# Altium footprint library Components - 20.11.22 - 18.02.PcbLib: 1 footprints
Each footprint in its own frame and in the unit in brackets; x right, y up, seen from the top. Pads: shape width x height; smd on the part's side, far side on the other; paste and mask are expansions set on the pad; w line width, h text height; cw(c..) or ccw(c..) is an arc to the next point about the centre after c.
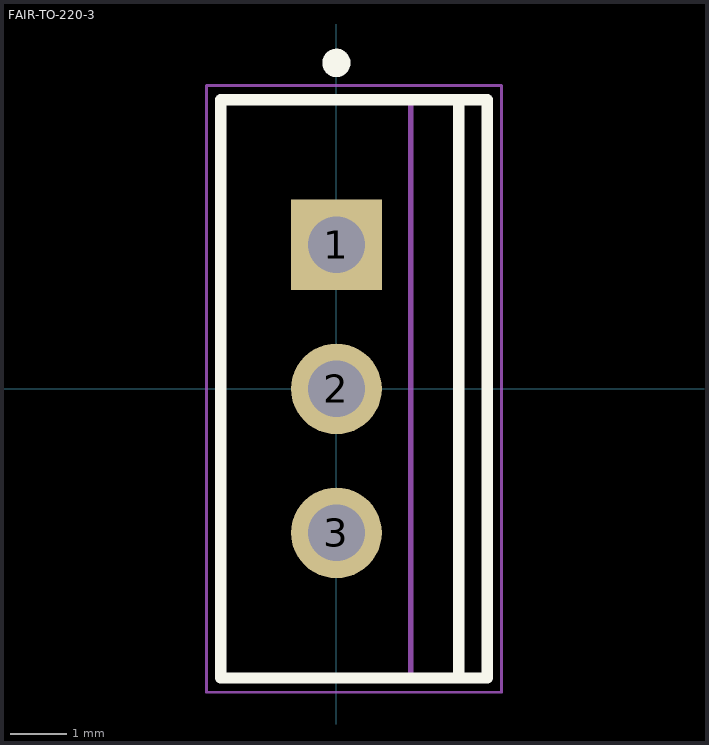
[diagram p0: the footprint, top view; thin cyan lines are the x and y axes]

## FAIR-TO-220-3 [mm] "FM, 3-Leads, Body 10.2x4.7mm, Pitch 2.54mm"
height 18.95
pads (3):
  rect 1.6x1.6 hole 1: 1(0,2.54)
  round 1.6 hole 1: 2(0,0) 3(0,-2.54)
Top Overlay:
  circle w0.25: c0,5.75 r0.125
  lines w0.2: 2.16,-5.1 2.16,5.1 ; -2.04,-5.1 -2.04,5.1 2.66,5.1 2.66,-5.1 -2.04,-5.1
Mechanical 13:
  lines w0.1: 1.31,-5.1 1.31,5.1 ; -2.04,-5.1 2.66,-5.1 2.66,5.1 -2.04,5.1 -2.04,-5.1
Mechanical 15:
  lines w0.05: -2.29,-5.35 2.91,-5.35 2.91,5.35 -2.29,5.35 -2.29,-5.35
  lines w0.1: -0.5,0 0.5,0 ; 0,-0.5 0,0.5
3D body: height 18.95, standoff 17.95, extent 1.31,-4.95 2.66,4.95
3D body: height 16.51, standoff 16.15, extent 1.31,-4.95 2.66,-1.8
3D body: height 16.51, standoff 16.15, extent 1.31,1.8 2.66,4.95
3D body: height 16.15, standoff 15.8, extent 1.31,-4.95 2.66,-1.8
3D body: height 16.15, standoff 15.8, extent 1.31,1.8 2.66,4.95
3D body: height 16.84, standoff 16.5, extent 1.31,-4.95 2.66,-1.765
3D body: height 16.84, standoff 16.5, extent 1.31,1.765 2.66,4.95
3D body: height 15.8, standoff 15.46, extent 1.31,-4.95 2.66,-1.765
3D body: height 15.8, standoff 15.46, extent 1.31,1.765 2.66,4.95
3D body: height 17.16, standoff 16.84, extent 1.31,-4.95 2.66,-1.663
3D body: height 17.16, standoff 16.84, extent 1.31,1.663 2.66,4.95
3D body: height 15.47, standoff 15.15, extent 1.31,-4.95 2.66,-1.663
3D body: height 15.47, standoff 15.15, extent 1.31,1.663 2.66,4.95
3D body: height 17.43, standoff 17.15, extent 1.31,-4.95 2.66,-1.497
3D body: height 17.43, standoff 17.15, extent 1.31,1.497 2.66,4.95
3D body: height 15.15, standoff 14.88, extent 1.31,-4.95 2.66,-1.497
3D body: height 15.15, standoff 14.88, extent 1.31,1.497 2.66,4.95
3D body: height 17.65, standoff 17.42, extent 1.31,-4.95 2.66,-1.273
3D body: height 17.65, standoff 17.42, extent 1.31,1.273 2.66,4.95
3D body: height 14.88, standoff 14.65, extent 1.31,-4.95 2.66,-1.273
3D body: height 14.88, standoff 14.65, extent 1.31,1.273 2.66,4.95
3D body: height 17.82, standoff 17.65, extent 1.31,-4.95 2.66,-1
3D body: height 17.82, standoff 17.65, extent 1.31,1 2.66,4.95
3D body: height 14.66, standoff 14.49, extent 1.31,-4.95 2.66,-1
3D body: height 14.66, standoff 14.49, extent 1.31,1 2.66,4.95
3D body: height 17.92, standoff 17.81, extent 1.31,-4.95 2.66,-0.689
3D body: height 17.92, standoff 17.81, extent 1.31,0.689 2.66,4.95
3D body: height 14.49, standoff 14.38, extent 1.31,-4.95 2.66,-0.689
3D body: height 14.49, standoff 14.38, extent 1.31,0.689 2.66,4.95
3D body: height 17.95, standoff 17.92, extent 1.31,-4.95 2.66,-0.351
3D body: height 17.95, standoff 17.92, extent 1.31,0.351 2.66,4.95
3D body: height 14.39, standoff 14.35, extent 1.31,-4.95 2.66,-0.351
3D body: height 14.39, standoff 14.35, extent 1.31,0.351 2.66,4.95
3D body: height 14.35, standoff 12.2, extent 1.31,-4.95 2.66,4.95
3D body: height 12.2, standoff 3, extent -2.04,-5.1 2.66,5.1
3D body: height 0, standoff -1.6, extent -0.265,-2.94 0.265,-2.14
3D body: height 3, standoff 0, extent -0.265,-3.3 0.265,-1.78
3D body: height 0, standoff -1.6, extent -0.265,-0.4 0.265,0.4
3D body: height 3, standoff 0, extent -0.265,-0.76 0.265,0.76
3D body: height 0, standoff -1.6, extent -0.265,2.14 0.265,2.94
3D body: height 3, standoff 0, extent -0.265,1.78 0.265,3.3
